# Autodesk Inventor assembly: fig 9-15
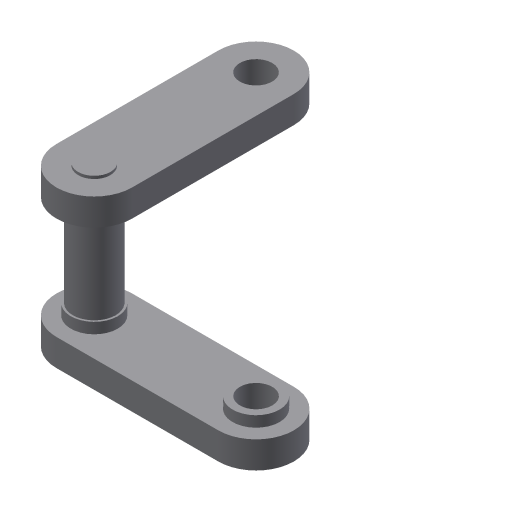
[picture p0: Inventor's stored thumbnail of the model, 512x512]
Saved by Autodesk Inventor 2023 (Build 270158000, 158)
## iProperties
Created: 2002-01
Part Number: fig 9-15
Document SubType Name: Assembly
Designer: ***
Control State: 0
Master: False
Checked Out: False
Shininess: 64.0
Length Units: 11269
Angle Units: 11279
Time Units: 11290
Mass Units: 11283
Length Display Precision: 3
Angle Display Precision: 2
Density: 0.0
Volumn: 0.0
Area: 0.0
PropertySet Name: Model Information
Author: ***
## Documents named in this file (3)
- D:\PROJECTS\Project 2022\Autodesk Inventor For Professional 2023\RESOURCES INVENTOR 2023\RESOURCES INVENTOR 2023\Inventor_2023_Part\Inventor_2023_Part\c09_Inv_2023_prt\fig 9-15.iam
- D:\PROJECTS\Project 2022\Autodesk Inventor For Professional 2023\RESOURCES INVENTOR 2023\RESOURCES INVENTOR 2023\Inventor_2023_Part\Inventor_2023_Part\c09_Inv_2023_prt\Part5.ipt
- D:\PROJECTS\Project 2022\Autodesk Inventor For Professional 2023\RESOURCES INVENTOR 2023\RESOURCES INVENTOR 2023\Inventor_2023_Part\Inventor_2023_Part\c09_Inv_2023_prt\Part6.ipt
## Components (3 placed, 2 different names)
1. Part5:1 — Insert:1, Angle:1
2. Part6:1 — Insert:1, Insert:2
3. Part5:2 — Insert:2, Angle:1
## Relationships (3: Insert 2, Angle 1)
- Insert:1: Part5:1 ↔ Part6:1
- Insert:2: Part6:1 ↔ Part5:2
- Angle:1: Part5:1 ↔ Part5:2
